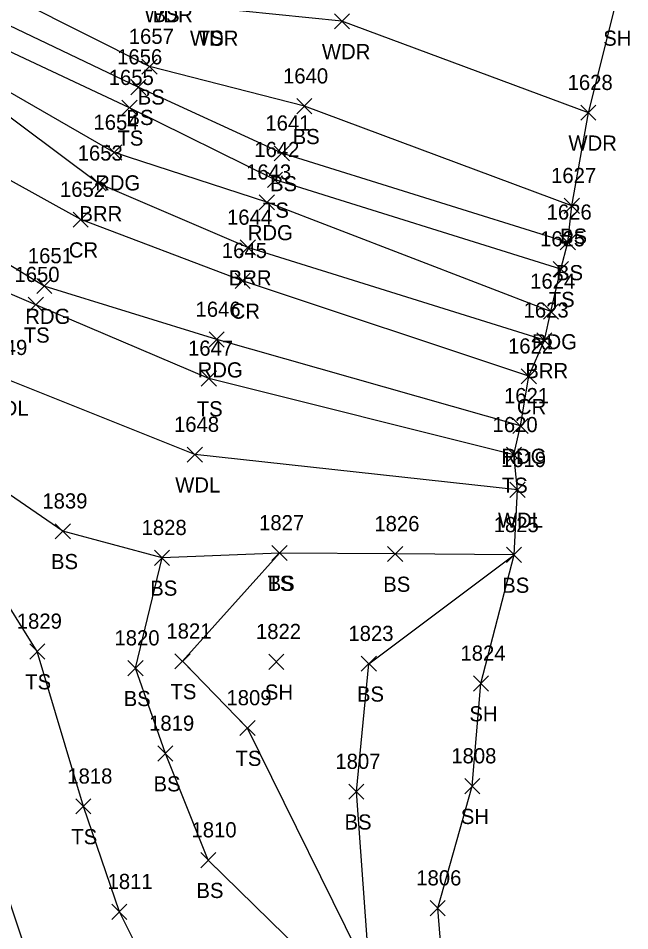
# Model space of a CAD drawing. Extents: x 1600281 to 1602254, y 862855 to 863227.
# Drawn here: x 1602169.1 to 1602249.7, y 862981.5 to 863101.9 of the extents above; entities that cross this region are included whole.
import ezdxf

# ---------------------------------------------------------------- set-up
doc = ezdxf.new("R2010")
doc.units = 0
for name, color, linetype in [('L_A', 7, 'Continuous'), ('L_I', 7, 'Continuous'), ('L_TIC', 7, 'Continuous'), ('LABL', 7, 'Continuous'), ('LAWA', 7, 'Continuous'), ('LELB', 7, 'Continuous'), ('LSOGP', 7, 'Continuous'), ('P_A', 7, 'Continuous'), ('P_I', 7, 'Continuous'), ('P_TIC', 7, 'Continuous'), ('PEU', 7, 'Continuous'), ('PRC', 7, 'Continuous')]:
    doc.layers.add(name, color=color, linetype=linetype)

msp = doc.modelspace()

# ---------------------------------------------------------------- linework, layer by layer
at = {"layer": 'L_TIC'}
for points in [[(1602210.76, 863100.45), (1602212.76, 863102.45)], [(1602212.76, 863100.45), (1602210.76, 863102.45)], [(1602185.39, 863094.47), (1602187.39, 863096.47)], [(1602187.39, 863094.47), (1602185.39, 863096.47)], [(1602183.9, 863091.77), (1602185.9, 863093.77)], [(1602185.9, 863091.77), (1602183.9, 863093.77)], [(1602205.81, 863089.25), (1602207.81, 863091.25)], [(1602207.81, 863089.25), (1602205.81, 863091.25)], [(1602182.74, 863089.05), (1602184.74, 863091.05)], [(1602184.74, 863089.05), (1602182.74, 863091.05)], [(1602243.26, 863088.39), (1602245.26, 863090.39)], [(1602245.26, 863088.39), (1602243.26, 863090.39)], [(1602202.83, 863083.04), (1602204.83, 863085.04)], [(1602204.83, 863083.04), (1602202.83, 863085.04)], [(1602178.65, 863079.08), (1602180.65, 863081.08)], [(1602180.65, 863079.08), (1602178.65, 863081.08)], [(1602201.94, 863079.55), (1602203.94, 863081.55)], [(1602203.94, 863079.55), (1602201.94, 863081.55)], [(1602241.08, 863076.12), (1602243.08, 863078.12)], [(1602243.08, 863076.12), (1602241.08, 863078.12)], [(1602240.55, 863071.3), (1602242.55, 863073.3)], [(1602242.55, 863071.3), (1602240.55, 863073.3)], [(1602198.34, 863070.62), (1602200.34, 863072.62)], [(1602200.34, 863070.62), (1602198.34, 863072.62)], [(1602239.62, 863067.77), (1602241.62, 863069.77)], [(1602241.62, 863067.77), (1602239.62, 863069.77)], [(1602170.4, 863063.07), (1602172.4, 863065.07)], [(1602172.4, 863063.07), (1602170.4, 863065.07)], [(1602237.45, 863058.38), (1602239.45, 863060.38)], [(1602239.45, 863058.38), (1602237.45, 863060.38)], [(1602193.2, 863053.35), (1602195.2, 863055.35)], [(1602195.2, 863053.35), (1602193.2, 863055.35)], [(1602191.35, 863043.31), (1602193.35, 863045.31)], [(1602193.35, 863043.31), (1602191.35, 863045.31)], [(1602233.44, 863043.27), (1602235.44, 863045.27)], [(1602235.44, 863043.27), (1602233.44, 863045.27)], [(1602233.91, 863038.66), (1602235.91, 863040.66)], [(1602235.91, 863038.66), (1602233.91, 863040.66)], [(1602173.95, 863033.2), (1602175.95, 863035.2)], [(1602175.95, 863033.2), (1602173.95, 863035.2)], [(1602202.52, 863030.33), (1602204.52, 863032.33)], [(1602204.52, 863030.33), (1602202.52, 863032.33)], [(1602202.52, 863030.33), (1602204.52, 863032.33)], [(1602204.52, 863030.33), (1602202.52, 863032.33)], [(1602187.04, 863029.7), (1602189.04, 863031.7)], [(1602189.04, 863029.7), (1602187.04, 863031.7)], [(1602187.04, 863029.7), (1602189.04, 863031.7)], [(1602189.04, 863029.7), (1602187.04, 863031.7)], [(1602217.77, 863030.21), (1602219.77, 863032.21)], [(1602219.77, 863030.21), (1602217.77, 863032.21)], [(1602233.46, 863030.08), (1602235.46, 863032.08)], [(1602235.46, 863030.08), (1602233.46, 863032.08)], [(1602170.58, 863017.35), (1602172.58, 863019.35)], [(1602172.58, 863017.35), (1602170.58, 863019.35)], [(1602189.74, 863016.05), (1602191.74, 863018.05)], [(1602191.74, 863016.05), (1602189.74, 863018.05)], [(1602202.11, 863015.99), (1602204.11, 863017.99)], [(1602204.11, 863015.99), (1602202.11, 863017.99)], [(1602183.54, 863015.14), (1602185.54, 863017.14)], [(1602185.54, 863015.14), (1602183.54, 863017.14)], [(1602214.3, 863015.73), (1602216.3, 863017.73)], [(1602216.3, 863015.73), (1602214.3, 863017.73)], [(1602229.09, 863013.13), (1602231.09, 863015.13)], [(1602231.09, 863013.13), (1602229.09, 863015.13)], [(1602198.31, 863007.25), (1602200.31, 863009.25)], [(1602200.31, 863007.25), (1602198.31, 863009.25)], [(1602187.47, 863003.89), (1602189.47, 863005.89)], [(1602189.47, 863003.89), (1602187.47, 863005.89)], [(1602227.95, 862999.59), (1602229.95, 863001.59)], [(1602229.95, 862999.59), (1602227.95, 863001.59)], [(1602212.66, 862998.86), (1602214.66, 863000.86)], [(1602214.66, 862998.86), (1602212.66, 863000.86)], [(1602176.66, 862996.92), (1602178.66, 862998.92)], [(1602178.66, 862996.92), (1602176.66, 862998.92)], [(1602193.13, 862989.83), (1602195.13, 862991.83)], [(1602195.13, 862989.83), (1602193.13, 862991.83)], [(1602223.39, 862983.49), (1602225.39, 862985.49)], [(1602225.39, 862983.49), (1602223.39, 862985.49)], [(1602181.41, 862983.02), (1602183.41, 862985.02)], [(1602183.41, 862983.02), (1602181.41, 862985.02)]]:
    msp.add_lwpolyline(points, dxfattribs=at)
at = {"layer": 'LABL'}
msp.add_lwpolyline([(1602238.45, 863059.38), (1602199.34, 863071.62), (1602179.65, 863080.08), (1602148.76, 863103.13), (1602128.22, 863117.32), (1602101.61, 863126.76), (1602102.3, 863128.31), (1602102.99, 863130.69), (1602105.29, 863133.38), (1602108.93, 863139.2)], dxfattribs=at)
at = {"layer": 'LAWA'}
for points in [[(1602244.26, 863089.39), (1602211.76, 863101.45), (1602194.35, 863103.22)], [(1602234.91, 863039.66), (1602192.35, 863044.31), (1602167.07, 863054.44), (1602131.76, 863070.49), (1602122.45, 863071.86), (1602110.76, 863082.89), (1602097.95, 863085.4), (1602096.24, 863076.79), (1602085.95, 863068.22)]]:
    msp.add_lwpolyline(points, dxfattribs=at)
at = {"layer": 'LELB'}
for points in [[(1602242.08, 863077.12), (1602206.81, 863090.25), (1602186.39, 863095.47), (1602152.13, 863112.74), (1602132.32, 863121.88), (1602102.99, 863130.69), (1602094.92, 863127.7), (1602081.09, 863125.32), (1602069.71, 863119.92), (1602067.84, 863117.44), (1602062.23, 863111.77), (1602054.78, 863103.53)], [(1602241.55, 863072.3), (1602203.83, 863084.04), (1602184.9, 863092.77), (1602150.82, 863109.07), (1602129.54, 863119.04), (1602102.3, 863128.31), (1602095.85, 863125.02), (1602082.9, 863122.06), (1602071.56, 863117.44), (1602069.71, 863115.85), (1602064.38, 863110.75), (1602060.62, 863098.3)], [(1602240.62, 863068.77), (1602202.94, 863080.55), (1602183.74, 863090.05), (1602150.19, 863105.82), (1602128.22, 863117.32)], [(1602234.44, 863044.27), (1602194.2, 863054.35), (1602171.4, 863064.07), (1602135.77, 863079.26), (1602125.86, 863083.34), (1602111.99, 863088), (1602098.79, 863097.89), (1602087.9, 863090.25), (1602076.95, 863086.28)], [(1602231.78, 862943.94), (1602226.26, 862961.53), (1602218.49, 862967.02), (1602194.13, 862990.83), (1602188.47, 863004.89), (1602184.54, 863016.14), (1602188.04, 863030.7), (1602174.95, 863034.2), (1602162.97, 863042.41), (1602150.21, 863055.3), (1602142.82, 863056.75), (1602118.66, 863061.18), (1602100.07, 863063.24)], [(1602197.44, 862931.78), (1602196.12, 862947.95), (1602189.93, 862968.99), (1602182.41, 862984.02), (1602177.66, 862997.92), (1602171.58, 863018.35), (1602165.76, 863027.59), (1602159.48, 863036.07), (1602148.99, 863052.05), (1602142.82, 863056.75)], [(1602197.44, 862931.78), (1602192.57, 862946.47), (1602183.09, 862964.15), (1602171.3, 862975.32), (1602165.37, 862992.89), (1602160.67, 863007.68), (1602154.53, 863022.83), (1602142.31, 863032.97)], [(1602215.42, 862975.54), (1602213.66, 862999.86), (1602215.3, 863016.73), (1602234.46, 863031.08), (1602218.77, 863031.21), (1602203.52, 863031.33), (1602188.04, 863030.7)], [(1602218.49, 862967.02), (1602215.42, 862975.54), (1602199.31, 863008.25), (1602190.74, 863017.05), (1602203.52, 863031.33)]]:
    msp.add_lwpolyline(points, dxfattribs=at)
at = {"layer": 'LSOGP'}
msp.add_lwpolyline([(1602226.26, 862961.53), (1602224.39, 862984.49), (1602228.95, 863000.59), (1602230.09, 863014.13), (1602234.46, 863031.08), (1602234.91, 863039.66), (1602234.44, 863044.27), (1602235.31, 863048.09), (1602236.4, 863054.64), (1602238.45, 863059.38), (1602239.32, 863063.19), (1602240.62, 863068.77), (1602241.55, 863072.3), (1602242.08, 863077.12), (1602244.26, 863089.39), (1602247.73, 863103.23)], dxfattribs=at)
at = {"layer": 'P_TIC'}
for points in [[(1602180.73, 863083.14), (1602182.73, 863085.14)], [(1602182.73, 863083.14), (1602180.73, 863085.14)], [(1602200.86, 863076.58), (1602202.86, 863078.58)], [(1602202.86, 863076.58), (1602200.86, 863078.58)], [(1602176.31, 863074.3), (1602178.31, 863076.3)], [(1602178.31, 863074.3), (1602176.31, 863076.3)], [(1602171.51, 863065.54), (1602173.51, 863067.54)], [(1602173.51, 863065.54), (1602171.51, 863067.54)], [(1602197.66, 863066.23), (1602199.66, 863068.23)], [(1602199.66, 863066.23), (1602197.66, 863068.23)], [(1602238.32, 863062.19), (1602240.32, 863064.19)], [(1602240.32, 863062.19), (1602238.32, 863064.19)], [(1602194.24, 863058.48), (1602196.24, 863060.48)], [(1602196.24, 863058.48), (1602194.24, 863060.48)], [(1602235.4, 863053.64), (1602237.4, 863055.64)], [(1602237.4, 863053.64), (1602235.4, 863055.64)], [(1602234.31, 863047.09), (1602236.31, 863049.09)], [(1602236.31, 863047.09), (1602234.31, 863049.09)]]:
    msp.add_lwpolyline(points, dxfattribs=at)
at = {"layer": 'PEU'}
for points in [[(1602239.32, 863063.19), (1602201.86, 863077.58), (1602181.73, 863084.14), (1602148.76, 863103.13), (1602126.1, 863112.3), (1602096.31, 863123.24), (1602085.65, 863117.24), (1602075.42, 863112.31), (1602066.28, 863103.64), (1602062.25, 863097.25), (1602069.56, 863092.76), (1602076.19, 863089.04)], [(1602235.31, 863048.09), (1602195.24, 863059.48), (1602172.51, 863066.54), (1602139.22, 863086.85), (1602117.28, 863097.26), (1602100.05, 863103.22), (1602086.41, 863097.2), (1602076.19, 863089.04)]]:
    msp.add_lwpolyline(points, dxfattribs=at)
at = {"layer": 'PRC'}
msp.add_lwpolyline([(1602236.4, 863054.64), (1602198.66, 863067.23), (1602177.31, 863075.3), (1602143.81, 863093.88), (1602121.55, 863104.55), (1602098.78, 863113.5), (1602079.15, 863104.73), (1602069.56, 863092.76)], dxfattribs=at)

# ---------------------------------------------------------------- texts
at = {"layer": 'L_A'}
for s, p in [('WDR', (1602185.7, 863101.33)), ('BS', (1602186.78, 863101.33)), ('WDR', (1602191.72, 863098.22)), ('TS', (1602192.76, 863098.22)), ('SH', (1602246.22, 863098.23)), ('WDR', (1602209.12, 863096.45)), ('BS', (1602184.83, 863090.47)), ('BS', (1602183.34, 863087.77)), ('TS', (1602182.15, 863085.05)), ('BS', (1602205.26, 863085.25)), ('WDR', (1602241.63, 863084.39)), ('BS', (1602202.27, 863079.04)), ('BRR', (1602177.14, 863075.08)), ('TS', (1602201.35, 863075.55)), ('BS', (1602240.52, 863072.12)), ('BRR', (1602196.83, 863066.62)), ('BS', (1602239.99, 863067.3)), ('TS', (1602239.03, 863063.77)), ('TS', (1602169.8, 863059.07)), ('BRR', (1602235.94, 863054.38)), ('WDL', (1602164.49, 863049.44)), ('TS', (1602192.61, 863049.35)), ('WDL', (1602189.77, 863039.31)), ('TS', (1602232.85, 863039.27)), ('WDL', (1602232.33, 863034.66)), ('BS', (1602173.39, 863029.2)), ('BS', (1602186.48, 863025.7)), ('BS', (1602186.48, 863025.7)), ('TS', (1602201.93, 863026.33)), ('BS', (1602201.96, 863026.33)), ('BS', (1602217.21, 863026.21)), ('BS', (1602232.9, 863026.08)), ('TS', (1602169.99, 863013.35)), ('BS', (1602182.98, 863011.14)), ('TS', (1602189.15, 863012.05)), ('SH', (1602201.6, 863011.99)), ('BS', (1602213.74, 863011.73)), ('SH', (1602228.57, 863009.13)), ('TS', (1602197.72, 863003.25)), ('BS', (1602186.91, 862999.89)), ('SH', (1602227.44, 862995.59)), ('BS', (1602212.1, 862994.86)), ('TS', (1602176.07, 862992.92)), ('BS', (1602192.57, 862985.83))]:
    msp.add_text(s, height=2, dxfattribs=at).set_placement(p)
at = {"layer": 'L_I'}
for s, p in [('1657', (1602183.65, 863098.47)), ('1656', (1602182.11, 863095.77)), ('1655', (1602181, 863093.05)), ('1640', (1602203.99, 863093.25)), ('1628', (1602241.52, 863092.39)), ('1641', (1602201.66, 863087.04)), ('1642', (1602200.2, 863083.55)), ('1653', (1602176.91, 863083.08)), ('1627', (1602239.34, 863080.12)), ('1626', (1602238.75, 863075.3)), ('1644', (1602196.6, 863074.62)), ('1625', (1602237.88, 863071.77)), ('1650', (1602168.57, 863067.07)), ('1623', (1602235.71, 863062.38)), ('1649', (1602164.32, 863057.44)), ('1647', (1602191.46, 863057.35)), ('1648', (1602189.61, 863047.31)), ('1620', (1602231.62, 863047.27)), ('1619', (1602232.73, 863042.66)), ('1839', (1602172.25, 863037.2)), ('1827', (1602200.83, 863034.33)), ('1827', (1602200.83, 863034.33)), ('1826', (1602216.03, 863034.21)), ('1825', (1602231.77, 863034.08)), ('1828', (1602185.34, 863033.7)), ('1828', (1602185.34, 863033.7)), ('1829', (1602168.88, 863021.35)), ('1821', (1602188.61, 863020.05)), ('1822', (1602200.42, 863019.99)), ('1823', (1602212.61, 863019.73)), ('1820', (1602181.76, 863019.14)), ('1824', (1602227.39, 863017.13)), ('1809', (1602196.53, 863011.25)), ('1819', (1602186.33, 863007.89)), ('1807', (1602210.89, 863002.86)), ('1808', (1602226.18, 863003.59)), ('1818', (1602175.54, 863000.92)), ('1810', (1602191.92, 862993.83)), ('1811', (1602180.85, 862987.02)), ('1806', (1602221.56, 862987.49))]:
    msp.add_text(s, height=2, dxfattribs=at).set_placement(p)
at = {"layer": 'P_A'}
for s, p in [('RDG', (1602179.22, 863079.14)), ('RDG', (1602199.34, 863072.58)), ('CR', (1602175.74, 863070.3)), ('RDG', (1602170, 863061.54)), ('CR', (1602197.09, 863062.23)), ('RDG', (1602236.81, 863058.19)), ('RDG', (1602192.73, 863054.48)), ('CR', (1602234.83, 863049.64)), ('RDG', (1602232.79, 863043.09))]:
    msp.add_text(s, height=2, dxfattribs=at).set_placement(p)
at = {"layer": 'P_I'}
for s, p in [('1654', (1602178.99, 863087.14)), ('1643', (1602199.12, 863080.58)), ('1652', (1602174.57, 863078.3)), ('1645', (1602195.92, 863070.23)), ('1651', (1602170.34, 863069.54)), ('1624', (1602236.58, 863066.19)), ('1646', (1602192.45, 863062.48)), ('1622', (1602233.66, 863057.64)), ('1621', (1602233.13, 863051.09))]:
    msp.add_text(s, height=2, dxfattribs=at).set_placement(p)

doc.saveas('drawing.dxf')
